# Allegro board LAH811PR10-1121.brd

Outline 292.9 x 84.65 mm; copper layers: TOP, GND1, IN1, GND2, VCC, IN2, GND3, IN3, GND4, BOTTOM. Coordinates in mm from the lower left corner of the outline.

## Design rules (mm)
net group 20: nets DDR_DRAMRST# DDR_DRAMRST#_R
net group CB: nets CBN CBP
net group CHG_CSI: nets CHG_CSIN CHG_CSIP
net group CHG_CSO: nets CHG_CSON CHG_CSOP
net group CLK_PCIE_P1: nets CLK_PCIE_N1 CLK_PCIE_P1
net group CLK_PCIE_P1_R: nets CLK_PCIE_N1_R CLK_PCIE_P1_R
net group DDR_C_DQS0: nets DDR_C_DQS0 DDR_C_DQS#0
net group DDR_C_DQS1: nets DDR_C_DQS1 DDR_C_DQS#1
net group DDR_C_DQS2: nets DDR_C_DQS2 DDR_C_DQS#2
net group DDR_C_DQS3: nets DDR_C_DQS3 DDR_C_DQS#3
net group DDR_D_DQS0: nets DDR_D_DQS0 DDR_D_DQS#0
net group DDR_D_DQS1: nets DDR_D_DQS1 DDR_D_DQS#1
net group DDR_D_DQS2: nets DDR_D_DQS2 DDR_D_DQS#2
net group DDR_D_DQS3: nets DDR_D_DQS3 DDR_D_DQS#3
net group EDP_AUXN: nets EDP_AUXN EDP_AUXN_C
net group EDP_AUXP: nets EDP_AUXP EDP_AUXP_C
net group EDP_TXN0: nets EDP_TXN0 EDP_TXN0_C
net group EDP_TXN1: nets EDP_TXN1 EDP_TXN1_C
net group EDP_TXN2: nets EDP_TXN2 EDP_TXN2_C
net group EDP_TXN3: nets EDP_TXN3 EDP_TXN3_C
net group EDP_TXP0: nets EDP_TXP0 EDP_TXP0_C
net group EDP_TXP1: nets EDP_TXP1 EDP_TXP1_C
net group EDP_TXP2: nets EDP_TXP2 EDP_TXP2_C
net group EDP_TXP3: nets EDP_TXP3 EDP_TXP3_C
net group N20151664: nets N20151644 N20151664
net group PCIE_CRX_C_DTX_3: nets PCIE_CRX_C_DTX_N3 PCIE_CRX_C_DTX_P3
net group PCIE_CRX_C_DTX_16: nets PCIE_CRX_C_DTX_N16 PCIE_CRX_C_DTX_P16
net group PCIE_CRX_DTX_3: nets PCIE_CRX_DTX_N3 PCIE_CRX_DTX_P3
net group PCIE_CRX_DTX_9: nets PCIE_CRX_DTX_N9 PCIE_CRX_DTX_P9
net group PCIE_CRX_DTX_10: nets PCIE_CRX_DTX_N10 PCIE_CRX_DTX_P10
net group PCIE_CRX_DTX_11: nets PCIE_CRX_DTX_N11 PCIE_CRX_DTX_P11
net group PCIE_CRX_DTX_12: nets PCIE_CRX_DTX_N12 PCIE_CRX_DTX_P12
net group PCIE_CRX_DTX_16: nets PCIE_CRX_DTX_N16 PCIE_CRX_DTX_P16
net group PCIE_CTX_C_DRX_3: nets PCIE_CTX_C_DRX_N3 PCIE_CTX_C_DRX_P3
net group PCIE_CTX_C_DRX_9: nets PCIE_CTX_C_DRX_N9 PCIE_CTX_C_DRX_P9
net group PCIE_CTX_C_DRX_10: nets PCIE_CTX_C_DRX_N10 PCIE_CTX_C_DRX_P10
net group PCIE_CTX_C_DRX_11: nets PCIE_CTX_C_DRX_N11 PCIE_CTX_C_DRX_P11
net group PCIE_CTX_C_DRX_12: nets PCIE_CTX_C_DRX_N12 PCIE_CTX_C_DRX_P12
net group PCIE_CTX_C_DRX_16: nets PCIE_CTX_C_DRX_N16 PCIE_CTX_C_DRX_P16
net group PCIE_CTX_DRX_3: nets PCIE_CTX_DRX_N3 PCIE_CTX_DRX_P3
net group PCIE_CTX_DRX_9: nets PCIE_CTX_DRX_N9 PCIE_CTX_DRX_P9
net group PCIE_CTX_DRX_10: nets PCIE_CTX_DRX_N10 PCIE_CTX_DRX_P10
net group PCIE_CTX_DRX_11: nets PCIE_CTX_DRX_N11 PCIE_CTX_DRX_P11
net group PCIE_CTX_DRX_12: nets PCIE_CTX_DRX_N12 PCIE_CTX_DRX_P12
net group PCIE_CTX_DRX_16: nets PCIE_CTX_DRX_N16 PCIE_CTX_DRX_P16
net group PECI: nets PCH_PCIE_WAKE# PCIE_WAKE#
net group REM_DIODE1: nets REM_DIODE1_N REM_DIODE1_P
net group REM_DIODE4: nets REM_DIODE4_N REM_DIODE4_P
net group SD_CLK_L: nets SD_CLK SD_CLK_L
net group SD_CMD_L: nets SD_CMD SD_CMD_L
net group SD_D2_L: nets SD_D2 SD_D2_L
net group SD_D3_L: nets SD_D3 SD_D3_L
net group SD_RCLK_M_L: nets SD_RCLK_M SD_RCLK_M_L
net group SD_RCLK_P_L: nets SD_RCLK_P SD_RCLK_P_L
net group SOC_SPI_0_CS#2: nets SOC_SPI_0_CS#2 SPI_0_CS#2_TPM
net group SOC_SPI_0_D2: nets SOC_SPI_0_D2_R SPI_0_D2_ROM
net group SOC_SPI_0_D3: nets SOC_SPI_0_D3_R SPI_0_D3_ROM
net group SPK-6/6/6: nets SPK_L-_R SPK_R-_R
net group SPK_L: nets SPK_L+_R SPK_L-
net group SPK_R: nets SPK_R+_R SPK_R-
net group SW_USB20_1_4: nets SW_USB20_1_N4 SW_USB20_1_P4
net group SW_USB20_1_4_R: nets SW_USB20_1_N4_R SW_USB20_1_P4_R
net group SW_USB20_1_8: nets SW_USB20_1_N8 SW_USB20_1_P8
net group SW_USB20_1_8_R: nets SW_USB20_1_N8_R SW_USB20_1_P8_R
net group SW_USB20_2_4: nets SW_USB20_2_N4 SW_USB20_2_P4
net group SW_USB20_2_4_R: nets SW_USB20_2_N4_R SW_USB20_2_P4_R
net group SW_USB20_2_8: nets SW_USB20_2_N8 SW_USB20_2_P8
net group SW_USB20_2_8_R: nets SW_USB20_2_N8_R SW_USB20_2_P8_R
net group TBT_0_AUX: nets TBT_0_AUXN TBT_0_AUXP
net group TBT_0_AUX_R: nets TBT_0_AUXN_R TBT_0_AUXP_R
net group TBT_0_TRX_RD_DTX_1: nets TBT_0_TRX_RD_DTX_N1 TBT_0_TRX_RD_DTX_P1
net group TBT_0_TRX_RD_DTX_2: nets TBT_0_TRX_RD_DTX_N2 TBT_0_TRX_RD_DTX_P2
net group TBT_0_TTX_C_DRX_2: nets TBT_0_TTX_C_DRX_N2 TBT_0_TTX_C_DRX_P2
net group TBT_0_TTX_RD_DRX_1: nets TBT_0_TTX_RD_DRX_N1 TBT_0_TTX_RD_DRX_P1
net group TBT_0_TTX_RD_DRX_2: nets TBT_0_TTX_RD_DRX_N2 TBT_0_TTX_RD_DRX_P2
net group TBT_2_AUX: nets TBT_2_AUXN TBT_2_AUXP
net group TBT_2_AUX_R: nets TBT_2_AUXN_R TBT_2_AUXP_R
net group TBT_2_TRX_RD_DTX_1: nets TBT_2_TRX_RD_DTX_N1 TBT_2_TRX_RD_DTX_P1
net group TBT_2_TRX_RD_DTX_2: nets TBT_2_TRX_RD_DTX_N2 TBT_2_TRX_RD_DTX_P2
net group TBT_2_TTX_C_DRX_2: nets TBT_2_TTX_C_DRX_N2 TBT_2_TTX_C_DRX_P2
net group TBT_2_TTX_RD_DRX_1: nets TBT_2_TTX_RD_DRX_N1 TBT_2_TTX_RD_DRX_P1
net group TBT_2_TTX_RD_DRX_2: nets TBT_2_TTX_RD_DRX_N2 TBT_2_TTX_RD_DRX_P2
net group USB3_CRX_DTX_2: nets USB3_CRX_DTX_N2 USB3_CRX_DTX_P2
net group USB3_CTX_C_DRX_2: nets USB3_CTX_C_DRX_N2 USB3_CTX_C_DRX_P2
net group USB3_CTX_DRX_2: nets USB3_CTX_DRX_N2 USB3_CTX_DRX_P2
net group USB20_4: nets USB20_N4 USB20_P4
net group USB20_N10: nets USB20_N10 USB20_P10
net group USB20_N10_R: nets USB20_N10_R USB20_P10_R
net group 10: nets BEEP HPOUT-L HPOUT-L_L HPOUT-R HPOUT-R_L MIC2-VREFO-L MIC2-VREFO-R MONO_IN RING2_CONN SPKR
net group 12: nets CLK_BIASREF CPVEE H_CATERR# H_PROCHOT# H_PROCHOT#_R H_THERMTRIP# MBP2# MBP3# MIPI60_MBP0# MIPI60_MBP0#_R MIPI60_MBP1# MIPI60_MBP1#_R PROCHOT#_R1 THERMTRIP2# VCCST_PWRGD VCCST_PWRGD_CPU VCCSTPWRGOOD_TCSS
net group 15: nets ESPI_CLK ESPI_CLK_5105 SUSCLK SUSCLK_R TBT_L_ROM_CLK TBT_R_ROM_CLK VRALERT#
net group 18: nets PECI_EC PECI_EC_R VRALERT#_R
net group 38.4 MHZ: nets XTAL_38P4M_IN XTAL_38P4M_IN_CPU XTAL_38P4M_OUT XTAL_38P4M_OUT_CPU
net group CLK_S: nets MEC_XTAL1 MEC_XTAL2 MEC_XTAL2_R PCH_RTCX1 PCH_RTCX2 PCH_RTCX2_R TBT_L_XTAL_25_IN TBT_L_XTAL_25_IN_R TBT_L_XTAL_25_OUT TBT_L_XTAL_25_OUT_R TBT_R_XTAL_25_IN TBT_R_XTAL_25_IN_R TBT_R_XTAL_25_OUT TBT_R_XTAL_25_OUT_R
net group CNV_BRI /CNV_RGI: nets CNV_BRI_CRX_DTX CNV_BRI_CRX_R_DTX CNV_BRI_CTX_DRX CNV_BRI_CTX_R_DRX CNV_RGI_CRX_DTX CNV_RGI_CRX_R_DTX CNV_RGI_CTX_DRX CNV_RGI_CTX_R_DRX
net group CNVI-RX-50: nets CLK_CNV_CRX_DTX_N CLK_CNV_CRX_DTX_P CNV_CRX_DTX_N0 CNV_CRX_DTX_N1 CNV_CRX_DTX_P0 CNV_CRX_DTX_P1
net group CNVI-TX-50: nets CLK_CNV_CTX_DRX_N CLK_CNV_CTX_DRX_P CNV_CTX_DRX_N0 CNV_CTX_DRX_N1 CNV_CTX_DRX_P0 CNV_CTX_DRX_P1
net group DDR_COMP: nets DDR_COMP_0 DDR_COMP_1 DDR_COMP_2
net group DDR_DQS: nets DDR_A_DQS0 DDR_A_DQS1 DDR_A_DQS2 DDR_A_DQS3 DDR_A_DQS#0 DDR_A_DQS#1 DDR_A_DQS#2 DDR_A_DQS#3 DDR_B_DQS0 DDR_B_DQS1 DDR_B_DQS2 DDR_B_DQS3 DDR_B_DQS#0 DDR_B_DQS#1 DDR_B_DQS#2 DDR_B_DQS#3
net group DDRA_D0: nets DDR_A_D0_0 DDR_A_D0_1 DDR_A_D0_2 DDR_A_D0_3 DDR_A_D0_4 DDR_A_D0_5 DDR_A_D0_6 DDR_A_D0_7
net group DDRA_D1: nets DDR_A_D1_0 DDR_A_D1_1 DDR_A_D1_2 DDR_A_D1_3 DDR_A_D1_4 DDR_A_D1_5 DDR_A_D1_6 DDR_A_D1_7
net group DDRA_D2: nets DDR_A_D2_0 DDR_A_D2_1 DDR_A_D2_2 DDR_A_D2_3 DDR_A_D2_4 DDR_A_D2_5 DDR_A_D2_6 DDR_A_D2_7
net group DDRA_D3: nets DDR_A_D3_0 DDR_A_D3_1 DDR_A_D3_2 DDR_A_D3_3 DDR_A_D3_4 DDR_A_D3_5 DDR_A_D3_6 DDR_A_D3_7
net group DDRB_D0: nets DDR_B_D0_0 DDR_B_D0_1 DDR_B_D0_2 DDR_B_D0_3 DDR_B_D0_4 DDR_B_D0_5 DDR_B_D0_6 DDR_B_D0_7
net group DDRB_D1: nets DDR_B_D1_0 DDR_B_D1_1 DDR_B_D1_2 DDR_B_D1_3 DDR_B_D1_4 DDR_B_D1_5 DDR_B_D1_6 DDR_B_D1_7
net group DDRB_D2: nets DDR_B_D2_0 DDR_B_D2_1 DDR_B_D2_2 DDR_B_D2_3 DDR_B_D2_4 DDR_B_D2_5 DDR_B_D2_6 DDR_B_D2_7
net group DDRB_D3: nets DDR_B_D3_0 DDR_B_D3_1 DDR_B_D3_2 DDR_B_D3_3 DDR_B_D3_4 DDR_B_D3_5 DDR_B_D3_6 DDR_B_D3_7
net group DDRC_D0: nets DDR_C_D0_0 DDR_C_D0_1 DDR_C_D0_2 DDR_C_D0_3 DDR_C_D0_4 DDR_C_D0_5 DDR_C_D0_6 DDR_C_D0_7
net group DDRC_D1: nets DDR_C_D1_0 DDR_C_D1_1 DDR_C_D1_2 DDR_C_D1_3 DDR_C_D1_4 DDR_C_D1_5 DDR_C_D1_6 DDR_C_D1_7
net group DDRC_D2: nets DDR_C_D2_0 DDR_C_D2_1 DDR_C_D2_2 DDR_C_D2_3 DDR_C_D2_4 DDR_C_D2_5 DDR_C_D2_6 DDR_C_D2_7
net group DDRC_D3: nets DDR_C_D3_0 DDR_C_D3_1 DDR_C_D3_2 DDR_C_D3_3 DDR_C_D3_4 DDR_C_D3_5 DDR_C_D3_6 DDR_C_D3_7
net group DDRD_D0: nets DDR_D_D0_0 DDR_D_D0_1 DDR_D_D0_2 DDR_D_D0_3 DDR_D_D0_4 DDR_D_D0_5 DDR_D_D0_6 DDR_D_D0_7
net group DDRD_D1: nets DDR_D_D1_0 DDR_D_D1_1 DDR_D_D1_2 DDR_D_D1_3 DDR_D_D1_4 DDR_D_D1_5 DDR_D_D1_6 DDR_D_D1_7
net group DDRD_D2: nets DDR_D_D2_0 DDR_D_D2_1 DDR_D_D2_2 DDR_D_D2_3 DDR_D_D2_4 DDR_D_D2_5 DDR_D_D2_6 DDR_D_D2_7
net group DDRD_D3: nets DDR_D_D3_0 DDR_D_D3_1 DDR_D_D3_2 DDR_D_D3_3 DDR_D_D3_4 DDR_D_D3_5 DDR_D_D3_6 DDR_D_D3_7
net group DIFF_RCOMP: nets PCIE_RCOMPN PCIE_RCOMPP TCRCOMP_DN TCRCOMP_DP
net group ESPI: nets ESPI_CS# ESPI_IO0 ESPI_IO0_R ESPI_IO1 ESPI_IO1_R ESPI_IO2 ESPI_IO2_R ESPI_IO3 ESPI_IO3_R ESPI_RESET#
net group HDA: nets DMIC_CLK12 DMIC_CLK12_R DMIC_DATA12 DMIC_DATA12_R HDA_BIT_CLK HDA_BIT_CLK_R HDA_SDIN0 HDA_SDIN0_R HDA_SDOUT HDA_SDOUT_R HDA_SYNC HDA_SYNC_R PCH_DMIC_CLK12 PCH_DMIC_DATA12 WOV_DMIC_CLK0 WOV_DMIC_DATA0
net group I2C/I2S-CLK: nets AMP_I2C_CLK AMP_I2S_BCLK AMP_I2S_BCLK_R AMP_I2S_LRCK AMP_I2S_LRCK_R CLK_SMB DAT_TP_SIO_I2C_CLK EC_AMP_I2C_CLK I2C1_PD_L_CLK I2C1_PD_R_CLK I2C2_PD_L_CLK I2C2_PD_R_CLK I2C3_PD_L_CLK I2C3_PD_R_CLK I2C_0_SCL I2C_0_SCL_R I2C_1_SCL I2C_1_SCL_R I2C_RT_L_SCL I2C_RT_R_SCL IMVP_SMBCLK IMVP_SMBCLK_VR ISH_I2C_1_SCL ISH_I2C_1_SCL_R PBAT_CHARGER_SMBCLK SMB_CLK SMB_CLK_MIPI60 SML0_SMBCLK SML0B_SMBCLK SML1_SMBCLK TAP_SMBCLK TAP_SMBCLK_R TBT_L_SMBCLK TBT_R_SMBCLK UPD_L_SMBCLK UPD_R_SMBCLK UPD_SMBCLK UPD_SMBCLK_Q
net group I2C/I2S-DATA: nets AMP_I2C_DAT AMP_I2S_OUT AMP_I2S_OUT_R CLK_TP_SIO_I2C_DAT DAT_SMB EC_AMP_I2C_DAT I2C1_PD_L_DAT I2C1_PD_R_DAT I2C2_PD_L_DAT I2C2_PD_R_DAT I2C3_PD_L_DAT I2C3_PD_R_DAT I2C_0_SDA I2C_0_SDA_R I2C_1_SDA I2C_1_SDA_R I2C_RT_L_SDA I2C_RT_R_SDA IMVP_SMBDAT IMVP_SMBDAT_VR ISH_I2C_1_SDA ISH_I2C_1_SDA_R PBAT_CHARGER_SMBDAT SMB_DATA SMB_DATA_MIPI60 SML0_SMBDATA SML0B_SMBDATA SML1_SMBDATA TAP_SMBDAT TAP_SMBDAT_R TBT_L_SMBDAT TBT_R_SMBDAT UPD_L_SMBDAT UPD_R_SMBDAT UPD_SMBDAT UPD_SMBDAT_Q
net group PLAT_CLK: nets CLK_PCIE_N0 CLK_PCIE_N0_R CLK_PCIE_N4 CLK_PCIE_N4_R CLK_PCIE_P0 CLK_PCIE_P0_R CLK_PCIE_P4 CLK_PCIE_P4_R
net group PWR_GND: nets +1.8V_3.3V_ALW_VTR3 +3.3V_EC_PLL +3VS_TPM +CHG_SRC_20V +EC_DEBUG_VCC +PECI_VREF +RTC_CELL_VBAT +RTCVCC +VBATT +VR_CAP
net group RTC: nets PCH_RTCRST#
net group SD_DP: nets SD_LN0_M SD_LN0_P SD_LN1_M SD_LN1_P
net group SD_S: nets SD_CD# SD_REG2 SP7_SDWP
net group SENSE: nets VCCIN_AUX_VCCSENSE VCCIN_AUX_VCCSENSE_R VCCIN_AUX_VCCSENSE_VR VCCIN_AUX_VSSSENSE VCCIN_AUX_VSSSENSE_R VCCIN_AUX_VSSSENSE_VR VCCIN_SENSE VCCIN_SENSE_R VCCIN_SENSE_VR VSSIN_SENSE VSSIN_SENSE_R VSSIN_SENSE_VR
net group SOC_SPI_0_CLK: nets SOC_SPI_0_CLK_R SPI_0_CLK_ROM SPI_0_CLK_TPM
net group SOC_SPI_0_CS#0: nets SOC_SPI_0_CS#0_R
net group SOC_SPI_0_CS#1: nets SOC_SPI_0_CS#1_R
net group SOC_SPI_0_D0: nets SOC_SPI_0_D0_R SPI_0_D0_ROM SPI_0_D0_TPM
net group SOC_SPI_0_D1: nets SOC_SPI_0_D1_R SPI_0_D1_ROM SPI_0_D1_TPM
net group SPI_5_15: nets MIPI60_SPI0_IO2 MIPI60_SPI0_MOSI TBT_L_ROM_CS# TBT_L_ROM_DI TBT_L_ROM_DO TBT_R_ROM_CS# TBT_R_ROM_DI TBT_R_ROM_DO
net group SRCCLKREQ#: nets CLKREQ_PCIE#0 CLKREQ_PCIE#1 CLKREQ_PCIE#4
net group SVID: nets SOC_SVID_ALERT# SOC_SVID_CLK SOC_SVID_DAT SVID_ALERT# SVID_ALERT#_VR SVID_CLK SVID_CLK_VR SVID_DAT SVID_DAT_VR
net group TBT_CONN: nets TBT_0_TTX_C_DRX_N1 TBT_0_TTX_C_DRX_P1 TBT_2_TTX_C_DRX_N1 TBT_2_TTX_C_DRX_P1
net group TBT_SOC: nets TBT_0_TRX_C_RD_DTX_N0 TBT_0_TRX_C_RD_DTX_N1 TBT_0_TRX_C_RD_DTX_P0 TBT_0_TRX_C_RD_DTX_P1 TBT_0_TRX_DTX_N0 TBT_0_TRX_DTX_N1 TBT_0_TRX_DTX_P0 TBT_0_TRX_DTX_P1 TBT_0_TTX_C_RD_DRX_N0 TBT_0_TTX_C_RD_DRX_N1 TBT_0_TTX_C_RD_DRX_P0 TBT_0_TTX_C_RD_DRX_P1 TBT_0_TTX_DRX_N0 TBT_0_TTX_DRX_N1 TBT_0_TTX_DRX_P0 TBT_0_TTX_DRX_P1 TBT_2_TRX_C_RD_DTX_N0 TBT_2_TRX_C_RD_DTX_N1 TBT_2_TRX_C_RD_DTX_P0 TBT_2_TRX_C_RD_DTX_P1 TBT_2_TRX_DTX_N0 TBT_2_TRX_DTX_N1 TBT_2_TRX_DTX_P0 TBT_2_TRX_DTX_P1 TBT_2_TTX_C_RD_DRX_N0 TBT_2_TTX_C_RD_DRX_N1 TBT_2_TTX_C_RD_DRX_P0 TBT_2_TTX_C_RD_DRX_P1 TBT_2_TTX_DRX_N0 TBT_2_TTX_DRX_N1 TBT_2_TTX_DRX_P0 TBT_2_TTX_DRX_P1
net group THERMAL: nets REM_DIODE2_N REM_DIODE2_P REM_DIODE3_N REM_DIODE3_P
net group UART: nets TBT_0_LSX_RX TBT_0_LSX_RX_R TBT_0_LSX_TX TBT_0_LSX_TX_R TBT_2_LSX_RX TBT_2_LSX_RX_R TBT_2_LSX_TX TBT_2_LSX_TX_R
net group USB2.0: nets USB20_N1 USB20_N5 USB20_N5_R USB20_N8 USB20_N9 USB20_P1 USB20_P5 USB20_P5_R USB20_P8 USB20_P9
net group W2.7S8.1: nets MIPI60_CFG_STB0_DN MIPI60_CFG_STB1_DN MIPI60_CPU_JTAG_TCLK MIPI60_PCH_JTAG_TCLK
net group W15: nets TBT_L_CC1 TBT_L_CC2 TBT_R_CC1 TBT_R_CC2
nets with their own width: min track width 0.254; nets +1.8VS_AUDIO +3.3V_ALW_UE1 +3.3V_BAT_LDO +3.3V_TBT_L_ANA +3.3V_TBT_L_FLASH +3.3V_TBT_L_FLASH_R +3.3V_TBT_L_LC +3.3V_TBT_L_SX +3.3V_TBT_R_ANA +3.3V_TBT_R_FLASH +3.3V_TBT_R_FLASH_R +3.3V_TBT_R_LC +3.3V_TBT_R_SX +3.3VA_TBT_L +3.3VA_TBT_R +3V_1.8V_HDA +3V_NB_LID +3V_SPI +3VS_TS +AVDD1 +DVDD +DVDDIO +SD_VDD2 +V1.05A_BYPASS +VCC1P05_OUTPUT_PLL +VCC1V8_TBT_L_LDO +VCC1V8_TBT_R_LDO +VCCA_CLKLDO_1P8 +VCCDPHY_1P24 +VCCDSW_1P05 +VCCIO_OUT +VCCLDOSTD_OUT_0P85 +VCCPRTC_3P3 +VSS_PLL LDO2_CAP LDO3_CAP N59074258 N78166986
nets with their own width: min track width 0.305; nets +3.3V_TBT_L_SVR +3.3V_TBT_R_SVR CNV_WT_RCOMP CPU_EOPIO_RCOMP CPU_POPI_RCOMP CSI_RCOMP DP_RCOMP EDRAM_OPIO_RCOMP EMMC_RCOMP PCH_OPI_RCOMP SD3_RCOMP SNDW_RCOMP USB2_COMP
nets with their own width: min track width 0.381; nets +3.3V_TBT_L +3.3V_TBT_R HPOL_CONN HPOR_CONN LINE2-L LINE2-R
nets with their own width: min track width 0.508; nets +0.6V_VDDQP +1.1V_MEM +1.8V_PRIM +1.8VS +3V_NB_LID_R +3V_PRIM +3VALW +3VALW_DSW +3VALWP +3VLP +3VS +3VS_FP +3VS_SSD +5VALW +5VALWB +5VALWP +5VS_AUDIO +RTCVCC_R +V1.05A_MIPI60 +VCC3V3_TBT_L_LDO +VCC3V3_TBT_R_LDO +VIN_3V3_L_TBT +VIN_3V3_R_TBT +VNN_BYPASS B+
nets with their own width: min track width 0.762; nets +1.05V_VCCST +1.05V_VCCSTG +LCDVDD +SD_VDD1 +TBT_L_SVR_IND +TBT_R_SVR_IND +VCC1.05_OUT_FET +VCC1.05_OUT_PCH +VCC_SFR_OC +VCCST_CPU +VCCSTG_CPU +VCCSTG_OUT +VCCSTG_OUT_LGC
nets with their own width: min track width 1.016; nets +0.9V_TBT_L_LVR +0.9V_TBT_L_SVR +0.9V_TBT_R_LVR +0.9V_TBT_R_SVR +5VBS +5VS +INV_PWR_SRC RING2 SLEEVE SLEEVE_CONN
nets with their own width: min track width 1.27; nets +VDDQ_MEM
nets with their own width: min track width 1.524; nets +1.1V_MEMP +PVDD
nets with their own width: min track width 1.778; nets +0.6V_VDDQ
nets with their own width: min track width 2.032; nets +3VS_CR +3VS_WLAN +VCC1P8A
nets with their own width: min track width 3.048; nets +CHG_VIN_20V
nets with their own width: min track width 3.556; nets +5VALW_L_TBT +5VALWB_R_TBT +TBT_VBUS_L +TBT_VBUS_L_PD +TBT_VBUS_R +TBT_VBUS_R_PD

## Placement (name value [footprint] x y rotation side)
C1  0.1U_0201_10V6K  [C_0201]  132.12 61.06 90 bottom
C2  0.1U_0201_10V6K  [C_0201]  131.54 61.06 90 bottom
C3  0.1U_0201_10V6K  [C_0201]  131.81 62.17 90 top
C4  0.1U_0201_10V6K  [C_0201]  131.18 62.17 90 top
C5  0.1U_0201_10V6K  [C_0201]  130.85 63.55 90 top
C6  0.1U_0201_10V6K  [C_0201]  130.21 63.55 90 top
C7  0.1U_0201_10V6K  [C_0201]  130.95 61.04 90 bottom
C8  0.1U_0201_10V6K  [C_0201]  130.39 61.05 90 bottom
C9  0.1U_0201_10V6K  [C_0201]  132.07 63.57 90 top
C10  0.1U_0201_10V6K  [C_0201]  132.7 63.57 90 top
C37  1U_0201_6.3V6M  [C_0201]  100.5 72.34 270 bottom
C38  0.1U_0201_10V6K  [C_0201]  133.47 64.39 270 top
C41  10U_0402_6.3V6M  [C_0402]  132.79 66.36 90 top
C42  .1U_0402_16V7K~D  [C_0402]  185.61 26.74 0 top
C46  0.1U_0201_10V6K  [C_0201]  134.1 64.38 270 top
C47  10U_0402_6.3V6M  [C_0402]  134.58 66.36 90 top
C48  33P_0402_50V8J  [C_0402]  133.69 66.36 90 top
C49  0.1U_0402_25V6  [C_0402]  138.01 66.36 90 top
C50  1U_0603_25V6K  [C_0603]  140.55 66.36 270 top
C52  0.1U_0402_25V6  [C_0402]  137.12 66.36 90 top
C58  0.1U_0402_25V6  [C_0402]  136.23 66.36 90 top
C87  0.1U_0402_25V6  [C_0402]  95.9 69.44 0 bottom
C92  2.2U_0201_6.3V6M  [C_0201]  225.88 16.38 0 bottom
C94  10U_0402_6.3V6M  [C_0402]  191.43 43.2 0 bottom
C95  0.1U_0201_10V6K  [C_0201]  189.12 45.46 90 bottom
C96  0.1U_0201_10V6K  [C_0201]  186.21 37.91 270 bottom
C97  0.1U_0201_10V6K  [C_0201]  186.78 37.91 270 bottom
C100  0.1U_0201_10V6K  [C_0201]  90.49 75.18 270 bottom
C112  1U_0201_6.3V6M  [C_0201]  5.06 41.83 180 bottom
C200  0.1U_0201_16V6K  [C_0201]  89.19 75.11 270 bottom
C216  1U_0201_6.3V6M  [C_0201]  182.97 43.54 270 top
C217  2200P_0402_25V7K  [C_0402]  183.61 48.51 90 top
C218  0.1U_0201_10V6K  [C_0201]  181.95 50.61 0 top
C220  0.1U_0201_16V6K  [C_0201]  99.79 73.82 90 top
C227  1000P_0402_25V8J  [C_0402]  124.47 1.69 180 top
C229  1U_0201_6.3V6M  [C_0201]  122.1 5 0 top
C230  0.1U_0201_10V6K  [C_0201]  123.28 6.28 270 top
C233  0.1U_0201_10V6K  [C_0201]  259.46 10.71 180 top
C234  4700P_0402_25V7K  [C_0402]  272.89 41.22 180 top
C235  1U_0201_6.3V6M  [C_0201]  264.99 5.66 270 bottom
C237  2200P_0402_25V7K  [C_0402]  268.24 2.43 90 bottom
C245  3300P_0402_25V7K  [C_0402]  254.22 55.57 180 bottom
C246  1U_0201_10V6M  [C_0201]  255.87 50.74 270 bottom
C248  0.1U_0201_10V6K  [C_0201]  192.04 41.11 0 bottom
C252  1U_0201_6.3V6M  [C_0201]  197.47 39.18 0 bottom
C256  1U_0201_6.3V6M  [C_0201]  269.2 43.88 180 top
C276  0.1U_0201_10V6K  [C_0201]  275.1 42.16 270 top
C278  0.1U_0201_10V6K  [C_0201]  254.34 57.47 270 bottom
C285  0.1U_0201_16V6K  [C_0201]  100.98 73.58 90 bottom
C418  0.1U_0201_10V6K  [C_0201]  111.98 70.93 180 bottom
C419  0.1U_0201_25V6K  [C_0201]  109.79 66.69 90 bottom
C420  0.1U_0201_25V6K  [C_0201]  114.34 70.6 0 bottom
C421  10U_0402_6.3V6M  [C_0402]  185.54 45.56 90 bottom
C422  0.1U_0201_10V6K  [C_0201]  186.27 45.53 90 bottom
C451  0.1U_0201_10V6K  [C_0201]  127.14 64.08 270 top
C452  15P_0201_50V8J  [C_0201]  126.56 64.08 270 top
C453  0.1U_0201_10V6K  [C_0201]  182.21 30.29 270 bottom
C454  12P_0201_50V8J  [C_0201]  182.46 46.55 270 bottom
C455  68P_0201_50V8J  [C_0201]  183.1 46.55 270 bottom
C622  0.1U_0201_16V6K  [C_0201]  226.75 10.1 0 top
C628  10U_0402_10V6M  [C_0402]  226.02 13.15 0 bottom
C640  1U_0201_6.3V6M  [C_0201]  224.19 12.15 270 top
C750  680P_0402_50V7K  [C_0402]  203.29 22.17 270 bottom
C760  0.33U_0201_6.3V6M  [C_0201]  99.61 71.79 270 bottom
C761  0.33U_0201_6.3V6M  [C_0201]  203.59 16.65 90 bottom
C800  0.1U_0201_10V6K  [C_0201]  18 38.3 90 bottom
C801  0.1U_0201_10V6K  [C_0201]  227.72 15.94 270 bottom
C1040  1U_0201_6.3V6M  [C_0201]  195.54 28.48 90 bottom
C1124  10U_0603_25V6M  [C_0603]  61.67 11.36 225 bottom
C1125  10U_0603_25V6M  [C_0603]  229.6 14.32 90 bottom
C1131  0.1U_0402_25V6K~D  [C_0402]  199.05 23.56 180 bottom
C1132  22P_0402_50V8J  [C_0402]  201.89 20.44 90 bottom
C1223  10U_0603_25V6M  [C_0603]  94.35 69.86 270 bottom
C1224  0.1U_0402_25V6  [C_0402]  92.19 73.93 180 bottom
C1387  10U_0402_6.3V6M  [C_0402]  185.45 37.79 270 bottom
C1467  2200P_0402_25V7K  [C_0402]  184.49 48.51 90 top
C1468  0.1U_0201_10V6K  [C_0201]  185.35 50.74 0 top
C1469  1U_0201_6.3V6M  [C_0201]  185.13 42.74 0 top
C1539  0.1U_0201_10V6K  [C_0201]  166.21 66.73 270 top
C1540  0.1U_0201_10V6K  [C_0201]  161.76 64.46 270 top
C1544  0.1U_0201_10V6K  [C_0201]  88.43 62.53 270 bottom
C2990  1U_0201_6.3V6M  [C_0201]  259.32 42.87 270 bottom
C3011  1U_0201_6.3V6M  [C_0201]  168.34 3.35 270 top
C3314  1000P_0402_50V7K  [C_0402]  182.47 70.5 90 bottom
C3315  0.1U_0201_25V6K  [C_0201]  182.29 69.76 0 bottom
C4180  15P_0201_25V8J  [C_0201]  223.56 12.15 270 top
C4181  0.1U_0402_25V6K~D  [C_0402]  60.48 11.82 225 bottom
C4182  0.1U_0402_25V6K~D  [C_0402]  229.78 17.54 270 bottom
C4183  100P_0201_50V8J  [C_0201]  255.44 41.09 90 bottom
C4186  0.1U_0201_10V6K  [C_0201]  255.69 40.43 270 bottom
C4189  2200P_0402_25V7K  [C_0402]  192.83 38.68 180 bottom
C4195  33P_0201_50V8J  [C_0201]  112.9 59.31 180 bottom
C4197  10U_0402_10V6M  [C_0402]  156.3 66.44 90 top
C4198  0.1U_0201_10V6K  [C_0201]  157.04 66.71 90 top
C4199  1U_0201_6.3V6M  [C_0201]  99.77 72.38 180 bottom
C4201  0.1U_0201_10V6K  [C_0201]  192.88 20.85 0 bottom
C4202  0.1U_0201_10V6K  [C_0201]  194.27 28.48 90 bottom
C4203  0.1U_0201_10V6K  [C_0201]  106.9 61.36 180 bottom
C4204  1U_0201_10V6M  [C_0201]  26.76 2.23 180 bottom
C4205  2200P_0402_25V7K  [C_0402]  31.59 3.24 0 bottom
C4207  0.1U_0201_10V6K  [C_0201]  33.21 3.1 90 bottom
C4212  1U_0201_10V6M  [C_0201]  221.2 16.74 270 bottom
C4213  220P_0402_50V8K  [C_0402]  225.95 18.33 0 bottom
C4216  1U_0201_6.3V6M  [C_0201]  21.93 41.98 270 bottom
C4217  10U_0402_10V6M  [C_0402]  17.24 38.3 90 bottom
C4221  0.1U_0201_16V6K  [C_0201]  227.19 13.91 180 bottom
C4222  10U_0402_10V6M  [C_0402]  228.36 13.15 0 bottom
C4227  1U_0402_25V6K  [C_0402]  269.33 25.16 0 top
C4230  0.1U_0201_10V6K  [C_0201]  182.31 6.14 90 top
C4232  0.1U_0201_10V6K  [C_0201]  211.62 3.59 90 bottom
C4233  1U_0201_6.3V6M  [C_0201]  211.04 4.17 270 bottom
C4234  680P_0402_50V7K~D  [C_0402]  194.65 6.11 180 bottom
C4235  680P_0402_50V7K~D  [C_0402]  196.83 4.2 180 bottom
C4236  2200P_0402_25V7K  [C_0402]  210.63 8.78 180 bottom
C4237  15P_0402_50V8J  [C_0402]  209.01 10.41 90 bottom
C4238  1U_0201_6.3V6M  [C_0201]  208.24 10.7 90 bottom
C4239  0.1U_0201_10V6K  [C_0201]  207.67 10.7 90 bottom
C4240  4700P_0201_10V6K  [C_0201]  189.26 15.97 0 top
C4241  0.1U_0201_6.3V6K  [C_0201]  234.94 2.25 0 top
C4245  4.7U_0201_6.3V6M  [C_0201]  178.14 26.08 180 top
C4247  2200P_0402_25V7K  [C_0402]  167.97 5.66 270 top
CA1  0.1U_0402_25V6  [C_0402]  270.98 37.28 90 top
CA9  330P_0201_50V7K  [C_0201]  262.98 66.36 90 top
CA10  10U_0603_6.3V6M  [C_0603]  262.65 69.36 270 top
CA11  330P_0201_50V7K  [C_0201]  262.35 66.36 90 top
CA12  10U_0603_6.3V6M  [C_0603]  260.62 69.39 270 top
CA13  100P_0201_25V7K  [C_0201]  259.42 62.81 270 bottom
CA14  0.1U_0201_10V6K  [C_0201]  259.17 63.7 90 bottom
CA15  10U_0402_10V6M  [C_0402]  259.55 66.36 90 top
CA17  2.2U_0201_10V6K  [C_0201]  257.01 65.73 0 top
CA18  2.2U_0603_10V7K  [C_0603]  263.87 66.34 90 top
CA19  10U_0402_10V6M  [C_0402]  255.87 62.93 90 bottom
CA20  4.7U_0402_10V6M  [C_0402]  256.25 65.6 270 top
CA21  2.2U_0603_10V7K  [C_0603]  265.46 64.17 112.9 top
CA22  10U_0402_10V6M  [C_0402]  255.66 62.93 90 top
CA23  0.1U_0201_10V6K  [C_0201]  256.43 63.06 90 top
CA24  0.1U_0201_10V6K  [C_0201]  265.09 62.3 0 top
CA26  0.1U_0201_10V6K  [C_0201]  256.12 61.41 180 top
CA29  10U_0402_10V6M  [C_0402]  266.41 61.28 90 top
CA30  0.1U_0201_10V6K  [C_0201]  256.12 60.14 180 top
CA32  10U_0402_10V6M  [C_0402]  266.16 60.39 0 top
CA33  0.1U_0201_10V6K  [C_0201]  258.66 56.46 180 top
CA36  0.1U_0201_10V6K  [C_0201]  266.08 59.5 270 top
CA37  22P_0201_25V8  [C_0201]  264.83 58.87 270 top
CA38  10U_0402_6.3V6M  [C_0402]  266.79 59.23 0 top
CA39  10U_0402_6.3V6M  [C_0402]  258.13 55.67 270 top
CA40  0.1U_0201_10V6K  [C_0201]  256.12 59.25 180 top
CA46  0.22U_0201_6.3V6M  [C_0201]  261.96 60.52 270 bottom
CA47  0.22U_0201_6.3V6M  [C_0201]  261.96 61.79 270 bottom
CA48  0.22U_0201_6.3V6M  [C_0201]  260.06 62.81 270 bottom
CA51  10U_0402_10V6M  [C_0402]  265.16 63.06 0 top
CA52  0.1U_0201_10V6K  [C_0201]  255.36 60.01 0 bottom
CA54  0.1U_0201_10V6K  [C_0201]  258.66 57.09 180 top
CA55  1U_0201_6.3V6M  [C_0201]  265.22 57.04 90 top
CA57  10P_0201_50V8J  [C_0201]  260.69 56.71 90 top
CA58  330P_0201_50V7K  [C_0201]  276.39 67.4 90 bottom
CA59  330P_0201_50V7K  [C_0201]  273.75 61.8 180 bottom
CA64  33P_0201_50V8J  [C_0201]  258.2 54.04 180 top
CA78  0.1U_0402_10V7K  [C_0402]  267.43 60.77 90 bottom
CA79  0.1U_0402_10V7K  [C_0402]  265.65 69.28 270 bottom
CA80  0.1U_0402_10V7K  [C_0402]  259.93 63.57 90 bottom
CA81  0.1U_0402_10V7K  [C_0402]  268.31 60.77 90 bottom
CA82  0.1U_0402_10V7K  [C_0402]  264.76 69.28 270 bottom
CA83  0.1U_0402_10V7K  [C_0402]  263.49 61.41 90 bottom
CA84  330P_0201_50V7K  [C_0201]  265.77 63.06 180 bottom
CA85  330P_0201_50V7K  [C_0201]  269.75 61.8 180 bottom
CA86  2.2U_0603_10V7K  [C_0603]  267.91 57.83 270 top
CA87  2.2U_0603_10V7K  [C_0603]  27.87 20.77 0 top
CA88  0.1U_0402_25V6  [C_0402]  23.08 26.36 0 top
CA89  0.1U_0402_25V6  [C_0402]  24.86 26.36 0 top
CA90  0.1U_0402_25V6  [C_0402]  27.14 23.18 0 top
CA91  0.1U_0402_25V6  [C_0402]  20.34 24.22 180 top
CA92  0.1U_0402_25V6  [C_0402]  27.14 24.2 0 top
CA93  0.1U_0402_25V6  [C_0402]  20.28 22.29 180 top
CA94  0.1U_0402_25V6  [C_0402]  20.28 23.18 180 top
CA95  0.1U_0402_25V6  [C_0402]  268.44 30.68 90 top
CA96  0.1U_0402_25V6  [C_0402]  269.2 34.89 0 top
CA97  0.1U_0402_25V6  [C_0402]  272.25 34.74 0 top
CA98  0.1U_0402_25V6  [C_0402]  268.95 28.14 270 top
CA99  0.1U_0402_25V6  [C_0402]  270.73 28.14 270 top
CA100  0.1U_0402_25V6  [C_0402]  271.62 28.14 270 top
CA101  10U_0603_25V6M  [C_0603]  29.01 25.34 180 top
CA102  10U_0603_25V6M  [C_0603]  272.12 38.74 270 top
CA103  1U_0603_25V6K  [C_0603]  27.2 22.04 0 top
CA104  1U_0603_25V6K  [C_0603]  20.2 25.33 180 top
CA105  1U_0603_25V6K  [C_0603]  20.47 21.15 180 top
CA106  1U_0603_25V6K  [C_0603]  272.25 35.88 0 top
CA107  1U_0603_25V6K  [C_0603]  267.93 28.52 180 top
CA108  1U_0603_25V6K  [C_0603]  27.87 19.5 0 top
CA109  100P_0201_25V7K  [C_0201]  24.86 30.17 90 top
CA110  100P_0201_25V7K  [C_0201]  21.09 28.09 225 top
CA111  100P_0201_25V7K  [C_0201]  265.99 29.48 180 top
CA112  100P_0201_25V7K  [C_0201]  269.58 39.31 0 top
CA113  33P_0201_50V8J  [C_0201]  263.87 55.95 270 top
CA114  33P_0201_50V8J  [C_0201]  263.23 55.95 270 top
CA115  33P_0201_50V8J  [C_0201]  262.6 55.95 270 top
CA116  33P_0201_50V8J  [C_0201]  261.96 56.58 90 top
CA117  10U_0603_25V6M  [C_0603]  28.98 26.61 180 top
CA118  10U_0603_25V6M  [C_0603]  273.39 38.74 270 top
CC1  0.1U_0201_10V6K  [C_0201]  103.98 64.71 90 bottom
CC17  1U_0201_6.3V6M  [C_0201]  161.76 62.93 0 top
CC23  0.1U_0201_10V6K  [C_0201]  172.89 45.19 270 bottom
CC30  0.1U_0201_10V6K  [C_0201]  171.79 45.4 0 top
CC77  0.1U_0201_10V6K  [C_0201]  169.38 56.71 0 top
CC129  10U_0402_6.3V6M  [C_0402]  149.18 61.33 90 bottom
CC130  1U_0201_6.3V6K  [C_0201]  144.61 32.83 0 bottom
CC131  1U_0201_6.3V6K  [C_0201]  139.73 32.83 0 bottom
CC132  1U_0201_6.3V6K  [C_0201]  146.26 33.25 270 bottom
CC133  1U_0201_6.3V6K  [C_0201]  141.92 32.83 0 bottom
CC134  1U_0201_6.3V6K  [C_0201]  137.46 32.83 0 bottom
CC135  1U_0201_6.3V6K  [C_0201]  146.89 33.25 270 bottom
CC136  10U_0402_6.3V6M  [C_0402]  135.39 32.83 0 bottom
CC137  10U_0402_6.3V6M  [C_0402]  133.69 27.88 270 top
CC138  10U_0402_10V6M  [C_0402]  129.42 32.83 0 bottom
CC139  10U_0402_10V6M  [C_0402]  133.76 32.83 180 bottom
CC140  10U_0402_10V6M  [C_0402]  120.02 28.05 270 top
CC141  22U_0603_6.3V6M  [C_0603]  122.37 27.21 180 top
CC142  22U_0603_6.3V6M  [C_0603]  141.55 27.21 0 top
CC144  1U_0201_6.3V6M  [C_0201]  153.61 33.25 180 bottom
CC145  1U_0201_6.3V6M  [C_0201]  155.51 32.65 0 bottom
CC147  1U_0201_6.3V6M  [C_0201]  153.28 61.07 180 bottom
CC148  1U_0201_6.3V6M  [C_0201]  153.28 61.66 180 bottom
CC153  1U_0201_6.3V6M  [C_0201]  151.43 61.15 0 bottom
CC154  1U_0201_6.3V6M  [C_0201]  151.43 61.78 0 bottom
CC155  1U_0201_6.3V6M  [C_0201]  150.74 61.15 180 bottom
CC156  1U_0201_6.3V6M  [C_0201]  150.74 61.78 180 bottom
CC164  10P_0201_25V8  [C_0201]  176.07 42.21 270 bottom
CC167  2.2P_0201_25V  [C_0201]  174.8 43.62 0 bottom
CC168  2.2P_0201_25V  [C_0201]  173.46 44.6 90 bottom
CC170  1U_0201_6.3V6M  [C_0201]  171.99 48.36 90 top
CC171  0.1U_0201_10V6K  [C_0201]  172.56 48.36 90 top
CC173  1U_0201_6.3V6M  [C_0201]  162.42 48.6 180 top
CC174  1U_0201_6.3V6M  [C_0201]  162.43 50.11 180 top
CC175  1U_0201_6.3V6M  [C_0201]  162.43 49.34 180 top
CC176  47U_0603_6.3V6M  [C_0603]  175.41 46.29 0 bottom
CC177  1U_0201_6.3V6M  [C_0201]  173.5 50.96 270 bottom
CC180  1U_0201_6.3V6M  [C_0201]  172.93 44.09 90 top
CC181  0.1U_0201_10V6K  [C_0201]  172.93 42.84 270 top
CC182  1U_0201_6.3V6M  [C_0201]  173.56 42.84 270 top
CC183  1U_0201_6.3V6M  [C_0201]  162.52 42.28 270 top
CC184  4.7U_0402_6.3V6M  [C_0402]  172.84 43.56 0 bottom
CC185  1U_0201_6.3V6K  [C_0201]  173.37 41.39 90 bottom
CC188  10U_0402_10V6M  [C_0402]  148.29 61.33 90 bottom
CC189  1U_0201_6.3V6M  [C_0201]  155.51 33.21 0 bottom
CC191  1U_0201_6.3V6M  [C_0201]  126.3 44.51 90 top
CC260  1U_0201_6.3V6K  [C_0201]  172.81 41.39 90 bottom
CC308  22U_0603_6.3V6M  [C_0603]  147.15 61.21 90 bottom
CC386  1U_0201_6.3V6M  [C_0201]  140.53 63.31 180 bottom
CC394  0.1U_0201_10V6K  [C_0201]  167.76 8.78 180 top
CC395  1U_0201_6.3V6M  [C_0201]  147.16 30.51 90 bottom
CC511  0.1U_0402_25V6  [C_0402]  171.74 29.41 180 bottom
CC620  0.1U_0201_10V6K  [C_0201]  179.16 47.44 0 bottom
CC621  0.1U_0201_10V6K  [C_0201]  179.41 47.19 0 top
CC622  0.1U_0201_10V6K  [C_0201]  176.06 42.81 90 bottom
CC625  0.1U_0201_10V6K  [C_0201]  178.52 44.26 90 bottom
CC629  1U_0201_6.3V6M  [C_0201]  151.22 58.23 270 top
CC632  0.1U_0201_10V6K  [C_0201]  146.78 66.24 270 top
CC633  0.1U_0201_10V6K  [C_0201]  143.22 63.44 270 top
CC638  1U_0201_6.3V6M  [C_0201]  152.93 65.32 270 bottom
CC643  12P_0201_25V8J  [C_0201]  109.39 18.45 180 top
CC644  12P_0201_25V8J  [C_0201]  139.2 27.63 270 top
CC645  12P_0201_25V8J  [C_0201]  139.83 27.63 270 top
CC646  2.2P_0201_25V8C  [C_0201]  109.39 17.82 180 top
CC647  2.2P_0201_25V8C  [C_0201]  123.83 27.63 270 top
CC648  2.2P_0201_25V8C  [C_0201]  123.2 27.63 270 top
CC649  100P_0201_50V8J  [C_0201]  108.17 63.7 0 bottom
CC650  100P_0201_50V8J  [C_0201]  152.67 62.91 270 bottom
CC651  0.1U_0201_10V6K  [C_0201]  176.53 51.25 180 bottom
CC652  0.1U_0201_10V6K  [C_0201]  181.92 28.87 270 top
CC653  0.1U_0201_10V6K  [C_0201]  173.13 31.65 90 bottom
CC654  27P_0201_25V8  [C_0201]  169.64 42.02 270 top
CC655  33P_0201_50V8J  [C_0201]  165.82 46.51 90 top
CC656  33P_0201_50V8J  [C_0201]  166.45 47.09 270 top
CC657  33P_0201_50V8J  [C_0201]  168.99 48.32 270 top
CC658  33P_0201_50V8J  [C_0201]  157.82 33.25 90 top
CC659  33P_0201_50V8J  [C_0201]  161.57 39.17 270 top
CC660  12P_0201_25V8J  [C_0201]  138.06 27.63 270 top
CC661  12P_0201_25V8J  [C_0201]  122.5 8.84 270 top
CC662  12P_0201_25V8J  [C_0201]  125.1 27.63 270 top
CC663  2.2P_0201_25V8C  [C_0201]  137.42 27.63 270 top
CC664  2.2P_0201_25V8C  [C_0201]  124.47 27.63 270 top
CC665  2.2P_0201_25V8C  [C_0201]  121.86 8.84 270 top
CC666  0.1U_0201_10V6K  [C_0201]  151.43 62.42 0 bottom
CC667  0.1U_0201_10V6K  [C_0201]  150.74 62.42 180 bottom
CC668  0.1U_0201_10V6K  [C_0201]  146.26 61.87 90 bottom
CC707  0.1U_0402_10V7K  [C_0402]  196.28 20.82 90 bottom
CC721  0.1U_0201_10V6K  [C_0201]  153.29 32.58 180 bottom
CC727  2.2P_0201_50V8B  [C_0201]  160.55 37.3 90 top
CC735  0.1U_0201_25V6K  [C_0201]  126.38 61.06 90 bottom
CC736  0.1U_0201_25V6K  [C_0201]  126.95 61.06 90 bottom
CC737  0.1U_0201_25V6K  [C_0201]  128.19 58.04 0 top
CC738  0.1U_0201_25V6K  [C_0201]  118.96 60.14 90 bottom
CC739  0.1U_0201_25V6K  [C_0201]  122.51 57.09 180 top
CC740  0.1U_0201_10V6K  [C_0201]  164.96 8.96 0 top
CD3  10U_0402_6.3V6M  [C_0402]  112.61 28.52 270 top
CD4  10U_0402_6.3V6M  [C_0402]  154.65 17.14 270 top
CD5  10U_0402_6.3V6M  [C_0402]  141.43 17.94 180 top
CD6  10U_0402_6.3V6M  [C_0402]  154.82 21.07 270 top
CD7  10U_0402_6.3V6M  [C_0402]  122.82 15.83 90 top
CD8  10U_0402_6.3V6M  [C_0402]  168.24 13.91 270 top
CD9  10U_0402_6.3V6M  [C_0402]  154.82 12.56 270 top
CD10  10U_0402_6.3V6M  [C_0402]  141.18 13.88 180 top
CD11  10U_0402_6.3V6M  [C_0402]  153.51 26.99 90 top
CD12  10U_0402_6.3V6M  [C_0402]  122.82 12.05 270 top
CD13  1U_0201_10V6M  [C_0201]  168.24 21.4 270 top
CD14  1U_0201_10V6M  [C_0201]  154.53 13.37 0 top
CD15  1U_0201_10V6M  [C_0201]  154.27 26.87 90 top
CD16  1U_0201_10V6M  [C_0201]  167.98 14.67 90 top
CD17  1U_0201_10V6M  [C_0201]  160.75 8.96 180 top
CD18  1U_0201_10V6M  [C_0201]  154.52 17.85 0 top
CD19  1U_0201_10V6M  [C_0201]  159.17 28.43 180 top
CD20  1U_0201_10V6M  [C_0201]  155.11 10.83 180 top
CD21  1U_0201_10V6M  [C_0201]  168.24 18.48 270 top
CD22  1U_0201_10V6M  [C_0201]  168.24 19.88 270 top
CD23  1U_0201_10V6M  [C_0201]  163.48 8.8 0 top
CD24  1U_0201_10V6M  [C_0201]  157.92 27.04 90 top
CD25  1U_0201_10V6M  [C_0201]  165.35 27.89 90 top
CD26  1U_0201_10V6M  [C_0201]  159.48 8.32 90 top
CD27  2.2P_0201_50V8B  [C_0201]  165.96 27.86 90 top
CD28  2.2P_0201_50V8B  [C_0201]  158.55 27.04 90 top
CD29  1U_0201_10V6M  [C_0201]  141.4 21.5 180 top
CD30  1U_0201_10V6M  [C_0201]  154.53 14.13 0 top
CD31  1U_0201_10V6M  [C_0201]  141.21 13.05 180 top
CD32  1U_0201_10V6M  [C_0201]  154.9 26.87 90 top
CD33  1U_0201_10V6M  [C_0201]  147.92 8.93 0 top
CD34  1U_0201_10V6M  [C_0201]  141.27 18.77 180 top
CD35  1U_0201_10V6M  [C_0201]  141.33 17.18 180 top
CD36  1U_0201_10V6M  [C_0201]  151 28.76 270 top
CD37  1U_0201_10V6M  [C_0201]  154.53 21.88 0 top
CD38  1U_0201_10V6M  [C_0201]  155.11 10.2 180 top
CD39  1U_0201_10V6M  [C_0201]  151.7 27.29 90 top
CD40  1U_0201_10V6M  [C_0201]  144.46 26.91 90 top
CD41  1U_0201_10V6M  [C_0201]  144.88 8.98 0 top
CD42  1U_0201_10V6M  [C_0201]  150.24 8.9 0 top
CD43  2.2P_0201_50V8B  [C_0201]  127.09 27.04 90 top
CD44  2.2P_0201_50V8B  [C_0201]  141.46 22.39 180 top
CD45  12P_0201_50V8J  [C_0201]  164.76 27.88 90 top
CD46  12P_0201_50V8J  [C_0201]  156.27 27.16 90 top
CD47  12P_0201_50V8J  [C_0201]  143.82 26.91 90 top
CD48  12P_0201_50V8J  [C_0201]  141.46 23.02 180 top
CD49  12P_0201_50V8J  [C_0201]  122.44 25.65 90 top
CD50  12P_0201_50V8J  [C_0201]  109.46 24.42 180 top
CD51  1U_0201_10V6M  [C_0201]  122.52 22.13 0 top
CD52  1U_0201_10V6M  [C_0201]  136.24 21.5 0 top
CD53  1U_0201_10V6M  [C_0201]  136.24 14.39 0 top
CD54  1U_0201_10V6M  [C_0201]  123.11 12.99 180 top
CD55  1U_0201_10V6M  [C_0201]  138.62 27.64 270 top
CD56  1U_0201_10V6M  [C_0201]  122.52 19.78 0 top
CD57  1U_0201_10V6M  [C_0201]  129.89 8.67 0 top
CD58  1U_0201_10V6M  [C_0201]  136.24 16.42 0 top
CD59  1U_0201_10V6M  [C_0201]  136.24 19.59 0 top
CD60  1U_0201_10V6M  [C_0201]  123.11 9.69 180 top
CD61  1U_0201_10V6M  [C_0201]  131.92 8.67 0 top
CD62  1U_0201_10V6M  [C_0201]  127.48 8.67 0 top
CD63  1U_0201_10V6M  [C_0201]  135.69 26.91 90 top
CD64  1U_0201_10V6M  [C_0201]  125.79 27.04 90 top
CD65  2.2P_0201_50V8B  [C_0201]  136.24 23.28 0 top
CD66  2.2P_0201_50V8B  [C_0201]  123.2 25.65 90 top
CD67  1U_0201_10V6M  [C_0201]  122.52 13.62 0 top
CD68  1U_0201_10V6M  [C_0201]  109.39 22.26 180 top
CD69  1U_0201_10V6M  [C_0201]  122.52 22.77 0 top
CD70  1U_0201_10V6M  [C_0201]  109.46 13.75 180 top
CD71  1U_0201_10V6M  [C_0201]  109.39 16.61 180 top
CD72  1U_0201_10V6M  [C_0201]  109.39 17.18 180 top
CD73  1U_0201_10V6M  [C_0201]  123.11 10.32 180 top
CD74  1U_0201_10V6M  [C_0201]  122.52 20.36 0 top
CD75  1U_0201_10V6M  [C_0201]  114.9 8.7 0 top
CD76  1U_0201_10V6M  [C_0201]  134.46 27.5 270 top
CD77  1U_0201_10V6M  [C_0201]  113.63 8.7 0 top
CD78  1U_0201_10V6M  [C_0201]  120.49 8.32 0 top
CD79  1U_0201_10V6M  [C_0201]  119.2 26.79 90 top
CD80  1U_0201_10V6M  [C_0201]  111.82 27.67 90 top
CD81  2.2P_0201_50V8B  [C_0201]  109.46 25.05 180 top
CD83  10U_0402_6.3V6M  [C_0402]  158.71 7.94 90 top
CD84  10U_0402_6.3V6M  [C_0402]  157.16 27.13 90 top
CD85  10U_0402_6.3V6M  [C_0402]  141.52 9.21 180 top
CD86  10U_0402_6.3V6M  [C_0402]  152.46 27 90 top
CD87  10U_0402_6.3V6M  [C_0402]  136.58 26.74 90 top
CD88  10U_0402_6.3V6M  [C_0402]  125.28 8.67 0 top
CD89  10U_0402_6.3V6M  [C_0402]  111.06 27.57 90 top
CD90  10U_0402_6.3V6M  [C_0402]  111.56 8.67 0 top
CD91  12P_0201_50V8J  [C_0201]  136.24 22.64 0 top
CD303  10U_0402_6.3V6M  [C_0402]  122.82 23.58 90 top
CD304  10U_0402_6.3V6M  [C_0402]  136.33 20.61 0 top
CD305  10U_0402_6.3V6M  [C_0402]  109.37 14.64 180 top
CD306  10U_0402_6.3V6M  [C_0402]  109.56 19.28 180 top
CD307  10U_0402_6.3V6M  [C_0402]  136.33 17.31 0 top
CD308  10U_0402_6.3V6M  [C_0402]  122.82 18.65 270 top
CD309  0.1U_0402_25V6  [C_0402]  200.57 46.55 180 bottom
CD310  100P_0201_50V8J  [C_0201]  168.24 22.67 90 top
CD311  100P_0201_50V8J  [C_0201]  161.38 8.96 0 top
CD312  100P_0201_50V8J  [C_0201]  168.24 24.45 270 top
CD313  100P_0201_50V8J  [C_0201]  141.44 20.9 180 top
CD314  100P_0201_50V8J  [C_0201]  151.5 8.98 0 top
CD315  100P_0201_50V8J  [C_0201]  141.19 12.39 180 top
CD316  100P_0201_50V8J  [C_0201]  136.23 15.05 0 top
CD317  100P_0201_50V8J  [C_0201]  136.23 18.1 0 top
CD318  100P_0201_50V8J  [C_0201]  126.46 27.04 90 top
CD319  100P_0201_50V8J  [C_0201]  109.44 22.93 180 top
CD320  100P_0201_50V8J  [C_0201]  123.15 8.83 270 top
CD321  100P_0201_50V8J  [C_0201]  109.44 23.82 180 top
CE39  2200P_0402_50V7K  [C_0402]  184.44 24.93 180 top
CE42  0.1U_0201_10V6K  [C_0201]  178.65 24.73 0 top
CE43  0.1U_0201_10V6K  [C_0201]  182.4 25.71 90 top
CE44  1U_0201_6.3V6M  [C_0201]  181.84 25.7 90 top
CE45  0.1U_0201_10V6K  [C_0201]  173.95 16.76 90 top
CE46  10U_0402_6.3V6M  [C_0402]  173.19 14.24 270 top
CE47  22U_0603_6.3V6M  [C_0603]  173.69 19.53 270 top
CE48  0.1U_0201_10V6K  [C_0201]  174.58 19.25 270 top
CE49  0.1U_0201_10V6K  [C_0201]  174.58 16.76 90 top
CE50  0.1U_0201_10V6K  [C_0201]  184.65 10.77 270 top
CE51  0.1U_0201_10V6K  [C_0201]  185.21 10.77 270 top
CE52  12P_0402_50V8J  [C_0402]  171.47 15.2 90 top
CE53  68P_0402_50V8J  [C_0402]  172.3 14.24 270 top
CE54  0.1U_0201_10V6K  [C_0201]  176.51 3.91 180 top
CE55  100P_0201_50V8J  [C_0201]  140.2 56.23 90 top
CE56  0.1U_0201_10V6K  [C_0201]  186.55 9.49 270 top
CE57  100P_0201_50V8J  [C_0201]  137.27 43.2 90 top
CE58  100P_0201_50V8J  [C_0201]  200.18 66.01 0 bottom
CE60  100P_0201_50V8J  [C_0201]  36.03 61.28 90 bottom
CE61  0.1U_0402_25V6  [C_0402]  163.01 29.55 90 bottom
CE63  1U_0201_6.3V6M  [C_0201]  189.11 7.91 0 top
CE64  1U_0201_6.3V6M  [C_0201]  174.5 15.94 180 top
CE65  33P_0201_50V8J  [C_0201]  170.02 22.93 0 top
CE66  10P_0402_50V8J  [C_0402]  174.46 24.02 270 top
CE67  100P_0201_50V8J  [C_0201]  103.85 13.15 0 bottom
CE68  1U_0201_10V6M  [C_0201]  170.05 20.1 0 top
CE69  100P_0201_50V8J  [C_0201]  138.55 10.86 0 top
CE76  2200P_0402_50V7K  [C_0402]  182.66 24.93 180 top
CE79  0.1U_0201_10V6K  [C_0201]  189.08 22.64 180 top
CE86  2200P_0201_25V7K  [C_0201]  187.74 24.93 180 top
CE88  0.1U_0201_10V6K  [C_0201]  181.32 9.47 270 top
CE89  10P_0402_50V8J  [C_0402]  175.55 25.16 180 top
CE93  2200P_0402_50V7K  [C_0402]  186.21 24.93 180 top
CE104  2.2U_0201_6.3V6M  [C_0201]  171.94 19.52 180 top
CE105  10P_0402_50V8J  [C_0402]  171.46 18.53 270 top
CE106  2200P_0402_50V7K  [C_0402]  179.91 9.03 270 top
CE107  2200P_0402_50V7K  [C_0402]  179.91 10.78 270 top
CE108  0.1U_0201_10V6K  [C_0201]  181.95 10.74 270 top
CE109  10U_0402_10V6M  [C_0402]  185.38 8.98 180 top
CE312  0.1U_0402_25V6  [C_0402]  163.77 2.18 90 top
CE413  0.1U_0402_25V6  [C_0402]  27.78 20.64 90 bottom
CE429  0.1U_0402_25V6  [C_0402]  274.23 16.22 270 bottom
CE430  0.1U_0402_25V6  [C_0402]  109.56 57.29 180 bottom
CE432  4700P_0402_25V7K  [C_0402]  170.6 18.89 180 top
CH3  0.1U_0402_10V7K~D  [C_0402]  257.44 22.98 270 bottom
CH4  0.1U_0402_10V7K~D  [C_0402]  258.36 22.98 270 bottom
CH10  10P_0201_50V8J  [C_0201]  175.2 54.29 90 bottom
CH11  10P_0201_50V8J  [C_0201]  175.19 56.09 270 bottom
CH12  15P_0201_50V8J  [C_0201]  167.77 31.3 0 bottom
CH13  15P_0201_50V8J  [C_0201]  165.89 31.3 180 bottom
CH35  0.1U_0201_10V6K  [C_0201]  181.84 32.89 0 bottom
CH40  22P_0201_50V8J  [C_0201]  159.75 33.12 270 top
CH44  0.1U_0201_10V6K  [C_0201]  191.39 47.16 0 top
CH45  0.1U_0201_10V6K  [C_0201]  191.39 47.73 0 top
CH46  1U_0201_6.3V6K  [C_0201]  174.33 31.56 270 bottom
CH47  1U_0201_6.3V6K  [C_0201]  169.37 33.55 90 top
CH48  0.01U_0402_16V7K  [C_0402]  178.02 30.8 270 bottom
CH49  0.1U_0201_10V6K  [C_0201]  163.31 33.2 270 bottom
CH50  56P_0201_25V8J  [C_0201]  160.36 33.12 270 top
CH51  56P_0201_25V8J  [C_0201]  159.21 35.08 90 top
CH52  0.33U_0201_6.3V6M  [C_0201]  170.27 32.23 270 bottom
CH53  0.33U_0201_6.3V6M  [C_0201]  170.85 32.23 270 bottom
CH54  0.33U_0201_6.3V6M  [C_0201]  169.56 32.23 270 bottom
CH55  0.33U_0201_6.3V6M  [C_0201]  171.99 32.23 270 bottom
CH56  0.33U_0201_6.3V6M  [C_0201]  172.56 32.23 270 bottom
CH57  0.33U_0201_6.3V6M  [C_0201]  171.42 32.23 270 bottom
CLIP5  EMIST_SV-11A1M  [EMIST_SV-11A1M_1P]  190.55 2.63 180 bottom
CLIP6  EMIST_SV-11A1M  [EMIST_SV-11A1M_1P]  235.75 2.63 180 bottom
CLIP7  EMIST_SV-11A1M  [EMIST_SV-11A1M_1P]  110.57 2.63 180 bottom
CM1  0.1U_0201_25V6K  [C_0201]  30.91 62.82 90 top
CM2  0.1U_0201_25V6K  [C_0201]  279.3 53.26 90 bottom
CP10  10U_0402_10V6M  [C_0402]  261.25 33.05 270 top
CPD1  0.1U_0201_10V6K  [C_0201]  38.32 61.03 0 bottom
CPD2  220P_0201_25V7K  [C_0201]  22.9 38.38 180 bottom
CPD3  220P_0201_25V7K  [C_0201]  22.84 36.85 180 bottom
CPD4  10U_0402_10V6M  [C_0402]  28.13 30.71 270 bottom
CPD5  10U_0402_10V6M  [C_0402]  29.15 30.71 270 bottom
CPD6  4.7U_0402_6.3V6M  [C_0402]  28.01 41.49 90 bottom
CPD7  10U_0402_10V6M  [C_0402]  22.9 37.62 180 bottom
CPD8  22U_0603_10V6M  [C_0603]  34.61 31.36 270 bottom
CPD11  0.1U_0201_10V6K  [C_0201]  248.72 22.7 180 bottom
CPD12  220P_0201_25V7K  [C_0201]  267.56 39.2 0 top
CPD13  220P_0201_25V7K  [C_0201]  267.5 40.72 0 top
CPD14  10U_0402_10V6M  [C_0402]  262.27 33.05 270 top
CPD16  4.7U_0402_6.3V6M  [C_0402]  262.4 43.83 90 top
CPD17  10U_0402_10V6M  [C_0402]  267.5 39.96 0 top
CPD18  22U_0603_10V6M  [C_0603]  258.97 33.67 270 top
CPD19  10U_0603_25V6M  [C_0603]  263.22 32.78 0 top
CPD40  10U_0603_25V6M  [C_0603]  27.2 30.37 180 bottom
CPD41  1U_0402_25V6K  [C_0402]  259.73 31.2 180 top
CPD42  1U_0402_25V6K  [C_0402]  24.75 31.38 270 bottom
CPD47  10U_0603_25V6M  [C_0603]  27.2 29.15 180 bottom
CPD48  10U_0603_25V6M  [C_0603]  263.3 31.58 0 top
CPD49  1U_0402_25V6K  [C_0402]  30.85 25.23 0 bottom
CPD51  1U_0402_25V6K  [C_0402]  265.65 33.72 270 top
CR1  0.1U_0201_10V6K  [C_0201]  9.98 38.08 90 bottom
CR2  0.1U_0201_10V6K  [C_0201]  9.41 38.08 90 bottom
CR3  0.1U_0201_10V6K  [C_0201]  7.95 43.58 0 bottom
CR4  0.1U_0201_10V6K  [C_0201]  7.95 44.15 0 bottom
CR5  4.7U_0402_6.3V6M  [C_0402]  12.93 46.34 0 bottom
CR6  0.1U_0201_10V6K  [C_0201]  10.06 45.19 180 bottom
CR7  10U_0402_6.3V6M  [C_0402]  11.43 46.34 180 bottom
CR8  0.1U_0201_10V6K  [C_0201]  11.39 45.58 180 bottom
CR9  0.1U_0201_10V6K  [C_0201]  13.55 45.58 180 bottom
CR10  2.2P_0201_25V  [C_0201]  17.03 45.19 0 bottom
CR11  2.2P_0201_25V  [C_0201]  17.03 44.56 0 bottom
CR13  2.2P_0201_25V  [C_0201]  17.03 43.8 0 bottom
CR15  1U_0201_6.3V6M  [C_0201]  15.76 43.16 0 bottom
CR16  2.2P_0201_25V  [C_0201]  17.03 42.53 0 bottom
CR17  2.2P_0201_25V  [C_0201]  17.03 41.89 0 bottom
CR18  2.2P_0201_25V  [C_0201]  17.03 41.26 0 bottom
CR19  1U_0201_6.3V6M  [C_0201]  15.76 39.86 0 bottom
CR20  0.1U_0201_10V6K  [C_0201]  13.54 37.84 270 bottom
CR21  10U_0402_6.3V6M  [C_0402]  18.28 54.75 270 bottom
CR22  4.7U_0402_6.3V6M  [C_0402]  6.21 46.22 270 bottom
CR23  4.7U_0402_6.3V6M  [C_0402]  14.31 38.45 270 bottom
CR24  0.1U_0402_10V7K  [C_0402]  5.32 46.22 270 bottom
CR25  0.1U_0402_10V7K  [C_0402]  18.28 56.66 270 bottom
CS24  0.22U_0201_6.3V6M  [C_0201]  191.52 14.72 180 bottom
CS25  0.22U_0201_6.3V6M  [C_0201]  191.52 14.09 180 bottom
CS26  0.22U_0201_6.3V6M  [C_0201]  191.14 10.36 180 bottom
CS27  0.22U_0201_6.3V6M  [C_0201]  191.14 10.99 180 bottom
CS89  33P_0201_25V8J  [C_0201]  184.16 5.2 270 top
CS90  4.7U_0402_6.3V6M  [C_0402]  180.66 29 90 bottom
CS91  0.1U_0201_10V6K  [C_0201]  185.15 27.48 90 top
CS92  0.01U_0201_16V7  [C_0201]  183.61 5.2 270 top
CS93  47P_0201_25V8J  [C_0201]  185.71 27.48 90 top
CS94  1U_0201_6.3V6M  [C_0201]  176.62 7.23 0 top
CS95  220P_0201_25V7K  [C_0201]  179.92 4.54 270 top
CS96  0.22U_0201_6.3V6M  [C_0201]  191.52 18.94 180 bottom
CS97  0.22U_0201_6.3V6M  [C_0201]  191.52 19.58 180 bottom
CS98  0.22U_0201_6.3V6M  [C_0201]  191.52 16.32 180 bottom
CS99  0.22U_0201_6.3V6M  [C_0201]  191.52 16.96 180 bottom
CT1  0.22U_0201_6.3V6M  [C_0201]  26.93 51.04 90 bottom
CT2  0.22U_0201_6.3V6M  [C_0201]  26.35 51.04 90 bottom
CT3  0.22U_0201_6.3V6M  [C_0201]  28.2 51.04 90 bottom
CT4  0.22U_0201_6.3V6M  [C_0201]  27.62 51.04 90 bottom
CT5  0.22U_0201_6.3V6M  [C_0201]  30.16 51.04 90 bottom
CT6  0.22U_0201_6.3V6M  [C_0201]  30.74 51.04 90 bottom
CT7  0.22U_0201_6.3V6M  [C_0201]  28.89 51.04 90 bottom
CT8  0.22U_0201_6.3V6M  [C_0201]  29.47 51.04 90 bottom
CT9  0.22U_0201_6.3V6M  [C_0201]  265.94 47.74 90 bottom
CT10  0.22U_0201_6.3V6M  [C_0201]  266.57 47.74 90 bottom
CT11  0.22U_0201_6.3V6M  [C_0201]  267.84 47.74 90 bottom
CT12  0.22U_0201_6.3V6M  [C_0201]  267.21 47.74 90 bottom
CT13  0.22U_0201_6.3V6M  [C_0201]  270.38 47.74 90 bottom
CT14  0.22U_0201_6.3V6M  [C_0201]  269.75 47.74 90 bottom
CT15  0.22U_0201_6.3V6M  [C_0201]  268.48 47.74 90 bottom
CT16  0.22U_0201_6.3V6M  [C_0201]  269.11 47.74 90 bottom
CT30  0.22U_0201_6.3V6M  [C_0201]  10.47 70.03 90 bottom
CT31  0.22U_0201_6.3V6M  [C_0201]  11.04 70.03 90 bottom
CT32  0.22U_0201_6.3V6M  [C_0201]  10.77 79.56 180 top
CT33  0.22U_0201_6.3V6M  [C_0201]  10.77 78.99 180 top
CT34  10U_0603_25V6M  [C_0603]  25.97 26.76 0 bottom
CT37  10U_0603_25V6M  [C_0603]  270.73 26.21 180 top
CT38  0.22U_0201_6.3V6M  [C_0201]  280.13 67.7 0 bottom
CT39  0.22U_0201_6.3V6M  [C_0201]  280.13 67.12 0 bottom
CT40  0.22U_0201_6.3V6M  [C_0201]  281.55 62.34 0 top
CT41  0.22U_0201_6.3V6M  [C_0201]  281.55 62.91 0 top
CT42  27P_0201_25V8  [C_0201]  23.33 57.88 0 bottom
CT43  27P_0201_25V8  [C_0201]  22.71 57.88 180 bottom
CT44  27P_0201_25V8  [C_0201]  261.65 54.29 270 bottom
CT45  27P_0201_25V8  [C_0201]  261.65 54.98 90 bottom
CT49  2.2U_0201_6.3V6M  [C_0201]  28.7 56.99 315 top
CT50  2.2U_0201_6.3V6M  [C_0201]  28.79 54.38 0 top
CT51  2.2U_0201_6.3V6M  [C_0201]  28.07 55.74 90 top
CT52  1U_0201_6.3V6K  [C_0201]  27.43 55.74 90 top
CT53  1U_0201_6.3V6K  [C_0201]  27.39 54.38 0 top
CT54  1U_0201_6.3V6K  [C_0201]  27.39 56.92 0 top
CT55  47U_0603_6.3V6M  [C_0603]  23.52 49.91 180 bottom
CT56  18P_0201_25V8J  [C_0201]  24.45 51.04 90 bottom
CT57  2.2U_0201_6.3V6M  [C_0201]  28.79 55.02 0 top
CT58  2.2U_0201_6.3V6M  [C_0201]  25.97 53.41 225 top
CT59  2.2U_0201_6.3V6M  [C_0201]  26.8 54.29 270 top
CT60  2.2U_0201_6.3V6M  [C_0201]  25.34 55.58 180 top
CT61  1U_0201_6.3V6K  [C_0201]  28.79 55.65 0 top
CT62  1U_0201_6.3V6K  [C_0201]  23.65 54.57 270 bottom
CT63  1U_0201_6.3V6K  [C_0201]  24.22 54.57 270 bottom
CT64  1U_0201_6.3V6K  [C_0201]  26.8 56.38 90 top
CT68  2.2U_0201_6.3V6M  [C_0201]  268.5 51.84 0 top
CT69  2.2U_0201_6.3V6M  [C_0201]  265.94 50.48 270 top
CT70  1U_0201_6.3V6K  [C_0201]  268.5 52.41 0 top
CT71  1U_0201_6.3V6K  [C_0201]  263.32 51.17 270 bottom
CT72  1U_0201_6.3V6K  [C_0201]  263.91 51.17 270 bottom
CT73  1U_0201_6.3V6K  [C_0201]  267.21 51.25 270 top
CT74  2.2U_0201_6.3V6M  [C_0201]  268.71 51.21 180 top
CT75  1U_0201_6.3V6K  [C_0201]  267.27 52.69 90 top
CT76  2.2U_0201_6.3V6M  [C_0201]  267.91 52.69 90 top
CT77  2.2U_0201_6.3V6M  [C_0201]  268.57 53.88 90 top
CT78  1U_0201_6.3V6K  [C_0201]  267.3 53.88 0 top
CT79  47U_0603_6.3V6M  [C_0603]  261.81 47.11 90 bottom
CT80  18P_0201_25V8J  [C_0201]  261.56 46.32 180 bottom
CT81  1U_0201_6.3V6K  [C_0201]  265.94 53.33 90 top
CT82  2.2U_0201_6.3V6M  [C_0201]  266.57 51.25 270 top
CT84  2.2U_0201_6.3V6M  [C_0201]  266.03 52.48 0 top
CT200  10U_0402_10V6M  [C_0402]  23.67 55.76 180 bottom
CT201  10U_0402_10V6M  [C_0402]  263.35 52.22 180 bottom
CT206  100P_0201_50V8J  [C_0201]  11.43 67.76 180 top
CT207  100P_0201_50V8J  [C_0201]  9.58 67.76 0 top
CT210  470P_0402_50V7K  [C_0402]  256.38 47.19 270 top
CT211  1U_0201_6.3V6K  [C_0201]  258.28 50.74 270 top
CT212  0.1U_0201_10V6K  [C_0201]  259.04 47.69 0 top
CT302  18P_0201_25V8J  [C_0201]  26.23 56.38 90 top
CT303  10U_0402_10V6M  [C_0402]  25.83 47.88 0 bottom
CT304  10U_0402_10V6M  [C_0402]  260.68 51.46 180 bottom
CT305  18P_0201_25V8J  [C_0201]  266.7 53.33 90 top
CT306  100P_0201_50V8J  [C_0201]  275.91 56.89 90 bottom
CT307  100P_0201_50V8J  [C_0201]  275.91 58.69 270 bottom
CT310  0.1U_0201_25V6K  [C_0201]  9.49 77.37 90 top
CT311  0.1U_0201_25V6K  [C_0201]  10.08 77.38 90 top
CT312  0.1U_0201_25V6K  [C_0201]  9.49 74.96 90 top
CT313  0.1U_0201_25V6K  [C_0201]  10.12 74.96 90 top
CT314  0.1U_0201_25V6K  [C_0201]  282.61 66.24 90 top
CT315  0.1U_0201_25V6K  [C_0201]  282.61 64.89 270 top
CT316  0.1U_0201_25V6K  [C_0201]  283.2 66.24 90 top
CT317  0.1U_0201_25V6K  [C_0201]  283.17 64.89 270 top
CT318  1U_0402_25V6K  [C_0402]  26.81 25.68 180 bottom
CT319  1U_0402_25V6K  [C_0402]  29.55 27.27 180 bottom
CT325  1U_0402_25V6K  [C_0402]  259.55 28.47 180 top
CT338  2200P_0201_25V7K  [C_0201]  26.65 22.95 180 bottom
CT339  0.01U_0201_25V6K  [C_0201]  26.65 23.58 180 bottom
CT340  0.1U_0201_25V6K  [C_0201]  26.65 24.22 180 bottom
CT341  100P_0201_50V8J  [C_0201]  26.65 24.85 180 bottom
CT342  2200P_0201_25V7K  [C_0201]  30.95 23.2 0 bottom
CT343  1000P_0201_25V7K  [C_0201]  30.95 24.47 0 bottom
CT344  100P_0201_50V8J  [C_0201]  29.25 26.44 180 bottom
CT345  0.1U_0201_25V6K  [C_0201]  30.95 23.84 0 bottom
CT346  1U_0402_25V6K  [C_0402]  30.85 26.12 0 bottom
CT347  10U_0603_25V6M  [C_0603]  13.11 66.36 180 bottom
CT348  2200P_0201_25V7K  [C_0201]  269.17 22.73 0 top
CT349  0.01U_0201_25V6K  [C_0201]  269.17 23.28 0 top
CT350  0.1U_0201_25V6K  [C_0201]  269.27 23.87 0 top
CT351  100P_0201_50V8J  [C_0201]  269.27 24.43 0 top
CT352  2200P_0201_25V7K  [C_0201]  259.45 25.55 180 top
CT353  1000P_0201_25V7K  [C_0201]  259.45 26.82 180 top
CT354  100P_0201_50V8J  [C_0201]  261.15 28.78 0 top
CT355  0.1U_0201_25V6K  [C_0201]  259.45 26.18 180 top
CT356  1U_0402_25V6K  [C_0402]  259.55 27.58 180 top
CT357  10U_0603_25V6M  [C_0603]  282.73 58.87 0 bottom
CT361  1U_0201_6.3V6K  [C_0201]  21.31 48.38 180 bottom
CT362  470P_0402_50V7K  [C_0402]  25.35 49.11 180 bottom
CT363  0.1U_0201_10V6K  [C_0201]  27.43 47.94 270 bottom
CT365  47U_0603_6.3V6M  [C_0603]  22.89 54.29 180 bottom
CT366  47U_0603_6.3V6M  [C_0603]  262.38 51.27 270 bottom
CV633  2200P_0402_50V7K  [C_0402]  108.75 69.16 90 bottom
CV651  2200P_0402_50V7K  [C_0402]  113.37 68.78 90 bottom
CW1  0.1U_0201_10V6K  [C_0201]  248.78 7.35 270 bottom
CW2  0.01U_0201_16V7  [C_0201]  249.39 7.35 270 bottom
CW3  10U_0402_6.3V6M  [C_0402]  248.48 8.96 180 bottom
CW4  15P_0201_50V8J  [C_0201]  248.17 7.35 270 bottom
CW9  10U_0402_6.3V6M  [C_0402]  264.71 3.52 270 top
CW10  0.01U_0201_16V7  [C_0201]  262.12 7.36 270 top
CW11  15P_0201_50V8J  [C_0201]  259.46 11.35 180 top
CW12  0.1U_0201_10V6K  [C_0201]  262.7 7.36 270 top
